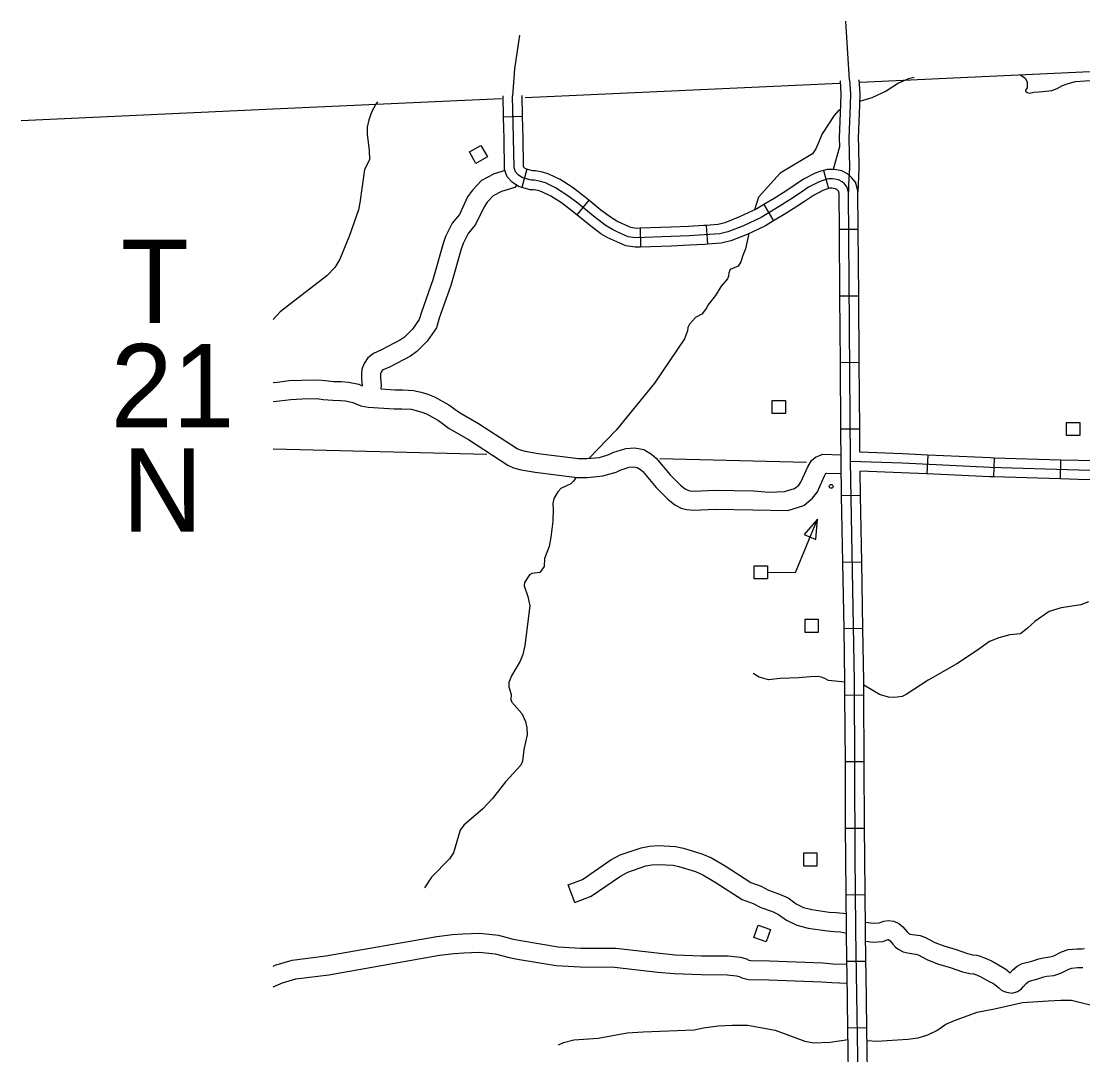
# Model space of a CAD drawing. Extents: x 1369885 to 1370219, y 379980 to 380218.
# Drawn here: x 1369978.02 to 1370011.52, y 380088.81 to 380121.42 of the extents above; entities that cross this region are included whole.
import ezdxf

# ---------------------------------------------------------------- set-up
doc = ezdxf.new("R2010")
doc.units = 0
for name, color, linetype in [('Default', 7, 'Continuous'), ('Level 1', 7, 'Continuous'), ('Level 30', 7, 'Continuous'), ('Level 32', 7, 'Continuous'), ('Level 35', 7, 'Continuous'), ('Level 45', 7, 'Continuous'), ('Level 46', 7, 'Continuous'), ('Level 5', 7, 'Continuous'), ('Level 56', 7, 'Continuous')]:
    doc.layers.add(name, color=color, linetype=linetype)

msp = doc.modelspace()

# ---------------------------------------------------------------- linework, layer by layer
at = {"layer": 'Level 1'}
for points in [[(1370004.498, 380119.502), (1370026.044, 380120.496), (1370044.91, 380121.323)], [(1369993.921, 380119.019), (1370003.848, 380119.473)], [(1369985.974, 380118.655), (1369993.176, 380118.985)]]:
    msp.add_lwpolyline(points, dxfattribs=at)
at = {"layer": 'Level 30'}
msp.add_lwpolyline([(1369978.02, 380118.291), (1369985.974, 380118.655)], dxfattribs=at)
at = {"layer": 'Level 32'}
for p, q in [((1369993.841, 380118.413), (1369993.245, 380118.4)), ((1369993.975, 380116.754), (1369993.819, 380116.178)), ((1370003.343, 380116.717), (1370003.5, 380116.141)), ((1369995.931, 380115.777), (1369995.554, 380115.315)), ((1370001.457, 380115.634), (1370001.765, 380115.123)), ((1369997.548, 380114.891), (1369997.568, 380114.295)), ((1369999.636, 380114.981), (1369999.676, 380114.386)), ((1370004.436, 380114.852), (1370003.839, 380114.847)), ((1370004.451, 380112.751), (1370003.854, 380112.747)), ((1370004.466, 380110.651), (1370003.87, 380110.647)), ((1370004.482, 380108.551), (1370003.885, 380108.547)), ((1370006.629, 380107.732), (1370006.602, 380107.136)), ((1370008.723, 380107.638), (1370008.705, 380107.042)), ((1370010.822, 380107.575), (1370010.804, 380106.978)), ((1370004.508, 380106.454), (1370003.911, 380106.443)), ((1370004.545, 380104.354), (1370003.949, 380104.343)), ((1370004.582, 380102.254), (1370003.986, 380102.243)), ((1370004.614, 380100.15), (1370004.017, 380100.147)), ((1370004.624, 380098.05), (1370004.028, 380098.047)), ((1370004.635, 380095.95), (1370004.038, 380095.947)), ((1370004.651, 380093.851), (1370004.055, 380093.845)), ((1370004.676, 380091.752), (1370004.08, 380091.744)), ((1370004.707, 380089.652), (1370004.111, 380089.643))]:
    msp.add_line(p, q, dxfattribs=at)
for points in [[(1369993.744, 380120.987), (1369993.582, 380119.922), (1369993.529, 380119.07)], [(1369993.245, 380118.4), (1369993.23, 380119.064)], [(1370004.471, 380085.49), (1370004.384, 380091.36), (1370004.364, 380092.736), (1370004.364, 380092.809), (1370004.341, 380095.069), (1370004.313, 380100.595), (1370004.191, 380107.531), (1370004.129, 380116.03), (1370004.077, 380116.198), (1370004.005, 380116.288), (1370003.925, 380116.358), (1370003.815, 380116.414), (1370003.697, 380116.438), (1370003.621, 380116.45), (1370003.498, 380116.45), (1370003.344, 380116.408), (1370003.2, 380116.355), (1370002.864, 380116.181), (1370002.579, 380115.986), (1370002.307, 380115.81), (1370001.936, 380115.574), (1370001.372, 380115.234), (1370000.811, 380114.971), (1370000.321, 380114.777), (1370000.066, 380114.711), (1369999.575, 380114.678), (1369999.096, 380114.65), (1369998.535, 380114.626), (1369997.407, 380114.588), (1369997.179, 380114.621), (1369996.844, 380114.768), (1369996.676, 380114.853), (1369996.481, 380114.966), (1369996.129, 380115.23), (1369995.539, 380115.712), (1369995.237, 380115.938), (1369994.879, 380116.165), (1369994.563, 380116.321), (1369994.403, 380116.368), (1369994.219, 380116.406), (1369994.12, 380116.406), (1369993.841, 380116.481), (1369993.704, 380116.571), (1369993.615, 380116.665), (1369993.572, 380116.797), (1369993.557, 380117.732), (1369993.529, 380119.07)], [(1369993.841, 380118.413), (1369993.827, 380119.077)], [(1369993.819, 380116.178), (1369993.717, 380116.206), (1369993.512, 380116.34), (1369993.352, 380116.509), (1369993.275, 380116.748), (1369993.259, 380117.727), (1369993.245, 380118.4)], [(1369993.975, 380116.754), (1369993.965, 380116.757), (1369993.897, 380116.801), (1369993.878, 380116.821), (1369993.87, 380116.846), (1369993.856, 380117.738), (1369993.841, 380118.413)], [(1369995.931, 380115.777), (1369995.723, 380115.947), (1369995.406, 380116.184), (1369995.025, 380116.425), (1369994.672, 380116.6), (1369994.475, 380116.657), (1369994.249, 380116.704), (1369994.159, 380116.704), (1369993.975, 380116.754)], [(1370003.343, 380116.717), (1370003.253, 380116.692), (1370003.08, 380116.629), (1370002.711, 380116.438), (1370002.413, 380116.234), (1370002.146, 380116.061), (1370001.778, 380115.828), (1370001.457, 380115.634)], [(1370004.436, 380114.852), (1370004.427, 380116.076), (1370004.345, 380116.34), (1370004.221, 380116.495), (1370004.094, 380116.607), (1370003.914, 380116.698), (1370003.75, 380116.731), (1370003.645, 380116.748), (1370003.458, 380116.748), (1370003.343, 380116.717)], [(1369995.554, 380115.315), (1369995.356, 380115.476), (1369995.067, 380115.692), (1369994.733, 380115.904), (1369994.454, 380116.042), (1369994.33, 380116.078), (1369994.188, 380116.107), (1369994.08, 380116.107), (1369993.819, 380116.178)], [(1370003.5, 380116.141), (1370003.435, 380116.123), (1370003.321, 380116.081), (1370003.018, 380115.925), (1370002.744, 380115.738), (1370002.468, 380115.559), (1370002.093, 380115.32), (1370001.765, 380115.123)], [(1370003.839, 380114.847), (1370003.831, 380115.984), (1370003.808, 380116.056), (1370003.788, 380116.081), (1370003.756, 380116.109), (1370003.716, 380116.129), (1370003.644, 380116.144), (1370003.598, 380116.151), (1370003.537, 380116.151), (1370003.5, 380116.141)], [(1369997.548, 380114.891), (1369997.424, 380114.887), (1369997.262, 380114.911), (1369996.971, 380115.038), (1369996.819, 380115.115), (1369996.646, 380115.215), (1369996.313, 380115.465), (1369995.931, 380115.777)], [(1370001.457, 380115.634), (1370001.231, 380115.498), (1370000.693, 380115.245), (1370000.228, 380115.061), (1370000.018, 380115.007), (1369999.636, 380114.981)], [(1369997.568, 380114.295), (1369997.391, 380114.289), (1369997.096, 380114.332), (1369996.717, 380114.498), (1369996.534, 380114.59), (1369996.316, 380114.717), (1369995.945, 380114.995), (1369995.554, 380115.315)], [(1369999.636, 380114.981), (1369999.557, 380114.976), (1369999.081, 380114.948), (1369998.523, 380114.924), (1369997.548, 380114.891)], [(1370001.765, 380115.123), (1370001.513, 380114.971), (1370000.93, 380114.697), (1370000.413, 380114.493), (1370000.114, 380114.415), (1369999.676, 380114.386)], [(1370003.854, 380112.747), (1370003.839, 380114.847)], [(1370004.451, 380112.751), (1370004.436, 380114.852)], [(1369999.676, 380114.386), (1369999.594, 380114.38), (1369999.111, 380114.352), (1369998.546, 380114.328), (1369997.568, 380114.295)], [(1370003.87, 380110.647), (1370003.854, 380112.747)], [(1370004.466, 380110.651), (1370004.451, 380112.751)], [(1370003.885, 380108.547), (1370003.87, 380110.647)], [(1370004.482, 380108.551), (1370004.466, 380110.651)], [(1370003.911, 380106.443), (1370003.892, 380107.527), (1370003.885, 380108.547)], [(1370004.487, 380107.819), (1370004.482, 380108.551)], [(1370015.013, 380107.203), (1370013.539, 380107.215), (1370011.383, 380107.259), (1370008.599, 380107.343), (1370005.817, 380107.471), (1370004.191, 380107.531)], [(1370006.629, 380107.732), (1370005.829, 380107.769), (1370004.487, 380107.819)], [(1370008.723, 380107.638), (1370008.61, 380107.641), (1370006.629, 380107.732)], [(1370010.822, 380107.575), (1370008.723, 380107.638)], [(1370012.919, 380107.526), (1370011.391, 380107.558), (1370010.822, 380107.575)], [(1370006.602, 380107.136), (1370005.804, 380107.173), (1370004.494, 380107.221)], [(1370004.508, 380106.454), (1370004.494, 380107.221)], [(1370008.705, 380107.042), (1370008.588, 380107.045), (1370006.602, 380107.136)], [(1370010.804, 380106.978), (1370008.705, 380107.042)], [(1370012.907, 380106.93), (1370011.376, 380106.961), (1370010.804, 380106.978)], [(1370003.949, 380104.343), (1370003.911, 380106.443)], [(1370004.545, 380104.354), (1370004.508, 380106.454)], [(1370003.986, 380102.243), (1370003.949, 380104.343)], [(1370004.582, 380102.254), (1370004.545, 380104.354)], [(1370004.017, 380100.147), (1370004.015, 380100.592), (1370003.986, 380102.243)], [(1370004.614, 380100.15), (1370004.612, 380100.598), (1370004.582, 380102.254)], [(1370004.028, 380098.047), (1370004.017, 380100.147)], [(1370004.624, 380098.05), (1370004.614, 380100.15)], [(1370004.038, 380095.947), (1370004.028, 380098.047)], [(1370004.635, 380095.95), (1370004.624, 380098.05)], [(1370004.055, 380093.845), (1370004.042, 380095.067), (1370004.038, 380095.947)], [(1370004.651, 380093.851), (1370004.639, 380095.072), (1370004.635, 380095.95)], [(1370004.08, 380091.744), (1370004.066, 380092.732), (1370004.065, 380092.806), (1370004.055, 380093.845)], [(1370004.676, 380091.752), (1370004.663, 380092.739), (1370004.662, 380092.812), (1370004.651, 380093.851)], [(1370004.707, 380089.652), (1370004.682, 380091.364), (1370004.676, 380091.752)], [(1370004.111, 380089.643), (1370004.085, 380091.355), (1370004.08, 380091.744)], [(1370004.142, 380087.543), (1370004.111, 380089.643)], [(1370004.739, 380087.552), (1370004.707, 380089.652)]]:
    msp.add_lwpolyline(points, dxfattribs=at)
at = {"layer": 'Level 35'}
for points in [[(1370006.195, 380119.652), (1370006.017, 380119.602), (1370005.704, 380119.468), (1370005.314, 380119.221), (1370004.863, 380119.008), (1370004.479, 380118.888)], [(1370009.531, 380119.734), (1370009.593, 380119.703), (1370009.702, 380119.622), (1370009.765, 380119.514), (1370009.769, 380119.382), (1370009.763, 380119.324), (1370009.723, 380119.268), (1370009.718, 380119.215), (1370009.769, 380119.171), (1370009.837, 380119.155), (1370009.977, 380119.187), (1370010.257, 380119.203), (1370010.542, 380119.242), (1370010.712, 380119.298), (1370010.88, 380119.39), (1370011.056, 380119.458), (1370011.296, 380119.518), (1370011.905, 380119.565)], [(1369989.262, 380118.874), (1369989.207, 380118.804), (1369989.087, 380118.577), (1369988.995, 380118.315), (1369988.935, 380118.078), (1369988.942, 380117.851), (1369989.005, 380117.355), (1369989.014, 380117.052), (1369988.849, 380116.74), (1369988.709, 380115.696), (1369988.661, 380115.471), (1369988.379, 380114.661), (1369988.073, 380113.911), (1369987.917, 380113.655), (1369987.667, 380113.392), (1369986.751, 380112.679), (1369986.191, 380112.255), (1369985.974, 380112.015)], [(1370003.874, 380118.64), (1370003.815, 380118.606), (1370003.677, 380118.45), (1370003.3, 380117.868), (1370003.156, 380117.545), (1370003.093, 380117.4), (1370002.987, 380117.237), (1370001.967, 380116.629), (1370001.288, 380115.87), (1370001.165, 380115.467)], [(1370000.983, 380114.722), (1370000.873, 380114.239), (1370000.788, 380114.034), (1370000.731, 380113.825), (1370000.643, 380113.694), (1370000.396, 380113.591), (1370000.348, 380113.478), (1370000.339, 380113.382), (1370000.306, 380113.289), (1370000.111, 380113.06), (1369999.933, 380112.768), (1369999.692, 380112.462), (1369999.647, 380112.365), (1369999.494, 380112.177), (1369999.303, 380112.071), (1369999.106, 380111.862), (1369999.062, 380111.761), (1369999.049, 380111.653), (1369998.95, 380111.399), (1369998.003, 380109.999), (1369996.793, 380108.519), (1369995.935, 380107.625)], [(1369995.53, 380107.033), (1369995.447, 380106.912), (1369995.362, 380106.825), (1369995.049, 380106.672), (1369994.953, 380106.574), (1369994.824, 380106.366), (1369994.794, 380106.198), (1369994.807, 380106.011), (1369994.795, 380105.644), (1369994.73, 380105.144), (1369994.68, 380104.843), (1369994.584, 380104.601)], [(1369994.584, 380104.601), (1369994.536, 380104.468), (1369994.52, 380104.217), (1369994.391, 380104.029), (1369994.13, 380103.997), (1369994.059, 380103.951), (1369993.9, 380103.715), (1369993.895, 380103.608), (1369994.005, 380103.272), (1369994.069, 380102.971), (1369993.917, 380101.719), (1369993.854, 380101.438), (1369993.761, 380101.232), (1369993.489, 380100.761), (1369993.408, 380100.555), (1369993.404, 380100.416), (1369993.479, 380100.175), (1369993.472, 380100.003), (1369993.498, 380099.936), (1369993.823, 380099.579), (1369993.938, 380099.32), (1369993.98, 380099.122), (1369993.982, 380098.903), (1369993.885, 380098.441), (1369993.841, 380098.069), (1369993.789, 380097.948), (1369993.301, 380097.419), (1369992.895, 380096.896), (1369992.592, 380096.564), (1369991.988, 380096.052), (1369991.877, 380095.893), (1369991.665, 380095.177), (1369991.535, 380094.986), (1369990.965, 380094.406), (1369990.745, 380094.069)], [(1370011.699, 380103.096), (1370011.463, 380103.005), (1370010.838, 380102.906), (1370010.464, 380102.799), (1370010.013, 380102.481), (1370009.778, 380102.273), (1370009.552, 380102.085), (1370009.222, 380102.057), (1370008.873, 380101.962), (1370008.581, 380101.849), (1370008.195, 380101.576), (1370007.547, 380101.14), (1370006.637, 380100.626), (1370005.948, 380100.175), (1370005.819, 380100.115), (1370005.594, 380100.076), (1370005.388, 380100.091), (1370005.11, 380100.175), (1370004.898, 380100.298), (1370004.614, 380100.473)], [(1370004.015, 380100.567), (1370003.496, 380100.619), (1370003.383, 380100.675), (1370003.27, 380100.722), (1370003.171, 380100.746), (1370002.916, 380100.732), (1370002.558, 380100.703), (1370001.974, 380100.675), (1370001.607, 380100.642), (1370001.305, 380100.727), (1370001.117, 380100.84)], [(1370004.713, 380089.261), (1370005.021, 380089.233), (1370005.997, 380089.294), (1370006.321, 380089.344), (1370006.628, 380089.437), (1370006.914, 380089.569), (1370007.202, 380089.769), (1370007.472, 380089.882), (1370008.19, 380090.148), (1370008.735, 380090.257), (1370009.615, 380090.451), (1370010.426, 380090.508), (1370010.825, 380090.534), (1370011.164, 380090.524), (1370012.097, 380090.293)], [(1369994.979, 380089.123), (1369995.135, 380089.195), (1369995.455, 380089.281), (1369996.228, 380089.328), (1369997.14, 380089.495), (1369997.644, 380089.531), (1369999.259, 380089.588), (1369999.555, 380089.652), (1370000.013, 380089.718), (1370000.458, 380089.744), (1370000.942, 380089.742), (1370001.809, 380089.581), (1370002.749, 380089.231), (1370003.037, 380089.184), (1370003.552, 380089.208), (1370004.116, 380089.289)]]:
    msp.add_lwpolyline(points, dxfattribs=at)
at = {"layer": 'Level 45'}
for points in [[(1370004.16, 380119.559), (1370004.039, 380121.423)], [(1370004.16, 380119.559), (1370004.187, 380119.135), (1370004.179, 380118.784), (1370004.135, 380117.736), (1370004.155, 380116.793), (1370004.131, 380116.266), (1370004.129, 380116.03)], [(1370004.458, 380119.577), (1370004.485, 380119.141), (1370004.477, 380118.774), (1370004.433, 380117.733), (1370004.439, 380117.467)], [(1370003.862, 380119.54), (1370003.888, 380119.129), (1370003.88, 380118.793), (1370003.836, 380117.739), (1370003.842, 380117.454)], [(1370003.842, 380117.454), (1370003.645, 380116.748)], [(1370004.439, 380117.467), (1370004.453, 380116.79), (1370004.429, 380116.258), (1370004.427, 380116.027)]]:
    msp.add_lwpolyline(points, dxfattribs=at)
at = {"layer": 'Level 46'}
for points in [[(1369993.288, 380116.707), (1369992.946, 380116.608), (1369992.542, 380116.392), (1369992.265, 380116.092), (1369992.109, 380115.876), (1369991.849, 380115.327), (1369991.621, 380115.054), (1369991.412, 380114.631), (1369991.337, 380114.408), (1369991.008, 380113.264), (1369990.647, 380112.238), (1369990.579, 380112.009), (1369990.37, 380111.708), (1369990.118, 380111.457), (1369989.991, 380111.366), (1369989.39, 380111.048), (1369989.135, 380110.938), (1369988.957, 380110.801), (1369988.847, 380110.618), (1369988.771, 380110.443), (1369988.763, 380110.301), (1369988.763, 380110.137), (1369988.783, 380109.916)], [(1369993.655, 380116.246), (1369993.597, 380116.176), (1369993.173, 380116.052), (1369992.913, 380115.913), (1369992.728, 380115.713), (1369992.625, 380115.57), (1369992.355, 380115.003), (1369992.124, 380114.726), (1369991.965, 380114.404), (1369991.907, 380114.231), (1369991.577, 380113.083), (1369991.215, 380112.054), (1369991.124, 380111.748), (1369990.83, 380111.324), (1369990.504, 380110.999), (1369990.305, 380110.857), (1369989.647, 380110.509), (1369989.44, 380110.42), (1369989.411, 380110.397), (1369989.379, 380110.344), (1369989.36, 380110.302), (1369989.359, 380110.283), (1369989.359, 380110.164), (1369989.38, 380109.937), (1369989.364, 380109.817)], [(1369985.974, 380110.023), (1369986.105, 380110.037), (1369986.477, 380110.081), (1369986.869, 380110.1), (1369987.389, 380110.11), (1369987.61, 380110.08), (1369987.882, 380110.058), (1369988.126, 380110.053), (1369988.344, 380110.037), (1369988.672, 380109.964), (1369988.783, 380109.916)], [(1369985.974, 380109.422), (1369986.173, 380109.444), (1369986.527, 380109.487), (1369986.889, 380109.504), (1369987.354, 380109.513), (1369987.545, 380109.487), (1369987.852, 380109.462), (1369988.098, 380109.457), (1369988.257, 380109.445), (1369988.487, 380109.394), (1369988.734, 380109.287), (1369988.968, 380109.245), (1369989.79, 380109.192), (1369990.033, 380109.192)], [(1369989.364, 380109.817), (1369989.81, 380109.789), (1369990.06, 380109.788)], [(1369990.06, 380109.788), (1369990.403, 380109.772), (1369990.64, 380109.718), (1369990.855, 380109.655), (1369991.065, 380109.572), (1369991.515, 380109.322), (1369991.851, 380109.072), (1369992.449, 380108.729), (1369993.67, 380107.94), (1369993.764, 380107.896), (1369993.927, 380107.852), (1369994.33, 380107.781), (1369995.607, 380107.624), (1369995.872, 380107.618), (1369996.266, 380107.659), (1369996.564, 380107.745), (1369996.686, 380107.811), (1369997.097, 380107.94), (1369997.383, 380107.959), (1369997.67, 380107.91), (1369997.911, 380107.762), (1369998.059, 380107.638), (1369998.496, 380107.111), (1369998.828, 380106.779), (1369998.969, 380106.664), (1369999.059, 380106.62), (1369999.123, 380106.602), (1369999.263, 380106.589), (1369999.913, 380106.62), (1370001.132, 380106.603)], [(1369990.033, 380109.192), (1369990.323, 380109.179), (1369990.489, 380109.141), (1369990.661, 380109.09), (1369990.809, 380109.032), (1369991.19, 380108.819), (1369991.523, 380108.572), (1369992.138, 380108.219), (1369993.381, 380107.416), (1369993.56, 380107.333), (1369993.798, 380107.269), (1369994.242, 380107.191), (1369995.564, 380107.028), (1369995.896, 380107.021), (1369996.38, 380107.071), (1369996.791, 380107.189), (1369996.919, 380107.259), (1369997.209, 380107.35), (1369997.351, 380107.359), (1369997.456, 380107.341), (1369997.562, 380107.276), (1369997.634, 380107.216), (1369998.055, 380106.709), (1369998.428, 380106.336), (1369998.645, 380106.159), (1369998.846, 380106.06), (1369999.014, 380106.014), (1369999.248, 380105.991), (1369999.923, 380106.023), (1370001.105, 380106.006)], [(1370001.132, 380106.603), (1370001.623, 380106.562), (1370002.111, 380106.58), (1370002.426, 380106.676), (1370002.56, 380106.786), (1370002.628, 380106.874), (1370002.841, 380107.361), (1370002.964, 380107.557), (1370003.09, 380107.664), (1370003.318, 380107.765), (1370003.891, 380107.744)], [(1370001.105, 380106.006), (1370002.21, 380105.987), (1370002.714, 380106.14), (1370002.991, 380106.368), (1370003.145, 380106.567), (1370003.37, 380107.081), (1370003.417, 380107.157), (1370003.434, 380107.164), (1370003.899, 380107.146)], [(1369995.495, 380093.609), (1369995.277, 380094.164), (1369995.728, 380094.342), (1369996.626, 380094.955), (1369996.926, 380095.112), (1369997.581, 380095.341), (1369997.849, 380095.392), (1369998.134, 380095.405), (1369998.669, 380095.378), (1369998.924, 380095.326), (1369999.504, 380095.15), (1369999.806, 380095.016), (1370000.235, 380094.766), (1370001.043, 380094.243), (1370001.367, 380094.125), (1370001.601, 380093.999), (1370001.949, 380093.879), (1370002.224, 380093.755), (1370002.477, 380093.568), (1370002.704, 380093.457), (1370002.969, 380093.385), (1370003.516, 380093.311), (1370003.74, 380093.292), (1370004.061, 380093.263)], [(1369995.495, 380093.609), (1369996.009, 380093.812), (1369996.934, 380094.442), (1369997.165, 380094.564), (1369997.736, 380094.763), (1369997.919, 380094.798), (1369998.133, 380094.808), (1369998.593, 380094.785), (1369998.777, 380094.747), (1369999.296, 380094.59), (1369999.534, 380094.484), (1369999.922, 380094.257), (1370000.775, 380093.706), (1370001.122, 380093.579), (1370001.361, 380093.451), (1370001.728, 380093.324), (1370001.92, 380093.237), (1370002.167, 380093.056), (1370002.492, 380092.897), (1370002.85, 380092.799), (1370003.451, 380092.717), (1370003.688, 380092.698), (1370003.877, 380092.681), (1370004.067, 380092.641)], [(1370004.66, 380092.987), (1370004.915, 380092.96), (1370005.093, 380092.974), (1370005.245, 380093.023), (1370005.378, 380093.041), (1370005.557, 380093.022), (1370005.711, 380092.945), (1370005.845, 380092.848), (1370005.98, 380092.69), (1370006.016, 380092.648), (1370006.034, 380092.636), (1370006.071, 380092.615), (1370006.152, 380092.596), (1370006.394, 380092.566), (1370006.562, 380092.505), (1370006.855, 380092.352), (1370007.134, 380092.24), (1370007.523, 380092.124), (1370007.885, 380091.998), (1370008.045, 380091.963), (1370008.181, 380091.95), (1370008.288, 380091.919), (1370008.39, 380091.876), (1370008.524, 380091.823), (1370008.659, 380091.755), (1370008.861, 380091.643), (1370008.985, 380091.574), (1370009.096, 380091.505), (1370009.232, 380091.39), (1370009.317, 380091.481), (1370009.449, 380091.603), (1370009.611, 380091.687), (1370009.91, 380091.764), (1370010.138, 380091.835), (1370010.281, 380091.87), (1370010.484, 380091.897), (1370010.604, 380091.933), (1370010.845, 380092.059), (1370011.057, 380092.13), (1370011.331, 380092.152), (1370011.502, 380092.152), (1370011.575, 380092.158)], [(1369985.974, 380091.602), (1369986.061, 380091.639), (1369986.567, 380091.789), (1369987.636, 380091.923), (1369991.136, 380092.543), (1369991.627, 380092.597), (1369991.954, 380092.621), (1369992.49, 380092.641), (1369993.08, 380092.58), (1369993.546, 380092.459), (1369993.788, 380092.412), (1369994.967, 380092.217), (1369995.683, 380092.173), (1369996.78, 380092.17), (1369998.173, 380092.011), (1369998.662, 380091.964), (1369999.49, 380091.932), (1370000.333, 380091.929), (1370000.711, 380091.887), (1370000.909, 380091.831), (1370000.982, 380091.791), (1370001.046, 380091.776), (1370001.631, 380091.767), (1370003.313, 380091.705), (1370003.633, 380091.679), (1370004.081, 380091.661)], [(1370004.668, 380092.386), (1370004.907, 380092.361), (1370005.209, 380092.384), (1370005.377, 380092.439), (1370005.386, 380092.44), (1370005.386, 380092.44), (1370005.401, 380092.433), (1370005.438, 380092.406), (1370005.528, 380092.301), (1370005.615, 380092.201), (1370005.719, 380092.129), (1370005.852, 380092.055), (1370006.044, 380092.008), (1370006.254, 380091.982), (1370006.322, 380091.958), (1370006.604, 380091.809), (1370006.937, 380091.676), (1370007.34, 380091.556), (1370007.723, 380091.423), (1370007.953, 380091.373), (1370008.067, 380091.362), (1370008.087, 380091.356), (1370008.164, 380091.323), (1370008.28, 380091.277), (1370008.381, 380091.227), (1370008.57, 380091.122), (1370008.681, 380091.06), (1370008.745, 380091.02), (1370008.872, 380090.914), (1370008.97, 380090.831), (1370009.113, 380090.776), (1370009.289, 380090.754), (1370009.462, 380090.8), (1370009.573, 380090.88), (1370009.649, 380090.962), (1370009.738, 380091.058), (1370009.794, 380091.11), (1370009.825, 380091.126), (1370010.073, 380091.19), (1370010.297, 380091.26), (1370010.39, 380091.282), (1370010.611, 380091.312), (1370010.83, 380091.379), (1370011.079, 380091.508), (1370011.178, 380091.541), (1370011.356, 380091.556), (1370011.524, 380091.556)], [(1369985.974, 380090.951), (1369986.266, 380091.078), (1369986.69, 380091.203), (1369987.726, 380091.333), (1369991.22, 380091.952), (1369991.682, 380092.003), (1369991.987, 380092.026), (1369992.47, 380092.043), (1369992.974, 380091.991), (1369993.414, 380091.877), (1369993.683, 380091.825), (1369994.9, 380091.623), (1369995.664, 380091.576), (1369996.745, 380091.573), (1369998.111, 380091.417), (1369998.622, 380091.369), (1369999.478, 380091.335), (1370000.299, 380091.333), (1370000.596, 380091.3), (1370000.682, 380091.275), (1370000.764, 380091.23), (1370000.969, 380091.18), (1370001.615, 380091.17), (1370003.278, 380091.109), (1370003.597, 380091.083), (1370004.09, 380091.064)]]:
    msp.add_lwpolyline(points, dxfattribs=at)
at = {"layer": 'Level 5'}
for points in [[(1369992.71, 380107.752), (1369985.974, 380107.92)], [(1370002.802, 380107.501), (1369998.169, 380107.617)]]:
    msp.add_lwpolyline(points, dxfattribs=at)
at = {"layer": 'Level 56'}
for points in [[(1369992.164, 380117.297), (1369992.522, 380117.505), (1369992.73, 380117.146), (1369992.372, 380116.938)], [(1370001.721, 380109.043), (1370001.721, 380109.457), (1370002.136, 380109.457), (1370002.136, 380109.043)], [(1370011.011, 380108.346), (1370011.011, 380108.76), (1370011.427, 380108.76), (1370011.427, 380108.346)], [(1370002.727, 380105.223), (1370003.102, 380105.067), (1370003.148, 380105.707)], [(1370001.153, 380103.827), (1370001.153, 380104.241), (1370001.569, 380104.241), (1370001.569, 380103.827)], [(1370002.759, 380102.134), (1370002.759, 380102.548), (1370003.174, 380102.548), (1370003.174, 380102.134)], [(1370002.713, 380094.76), (1370002.713, 380095.174), (1370003.129, 380095.174), (1370003.129, 380094.76)], [(1370001.137, 380092.505), (1370001.274, 380092.896), (1370001.666, 380092.758), (1370001.529, 380092.367)]]:
    msp.add_lwpolyline(points, close=True, dxfattribs=at)
msp.add_lwpolyline([(1370001.569, 380104.034), (1370002.45, 380104.027), (1370003.148, 380105.707)], dxfattribs=at)
msp.add_circle((1370003.581, 380106.743), 0.0597, dxfattribs=at)

# ---------------------------------------------------------------- texts
at = {"layer": 'Default'}
for s, p in [('T', (1369981.163, 380111.899)), ('21', (1369980.842, 380108.606)), ('N', (1369981.204, 380105.313))]:
    msp.add_text(s, height=2.63, dxfattribs=at).set_placement(p)

doc.saveas('drawing.dxf')
